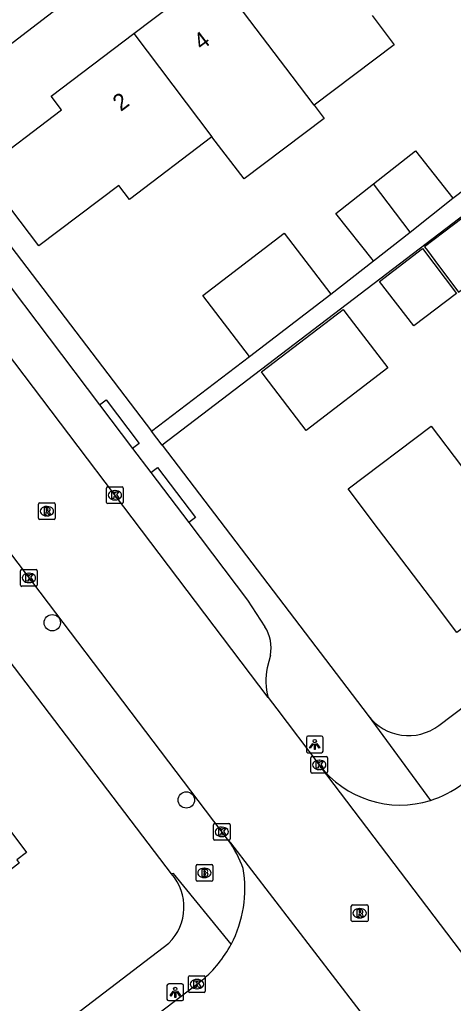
# Model space of a CAD drawing. Extents: x 160037 to 160839, y 385326 to 386441.
# Drawn here: x 160524.3 to 160550.3, y 385648.1 to 385707 of the extents above; entities that cross this region are included whole.
import ezdxf

# ---------------------------------------------------------------- set-up
doc = ezdxf.new("R2010")
doc.units = 0
for name, color, linetype in [('IMGEO_Boom', 7, 'Continuous'), ('IMGEO_Brandkraan', 7, 'Continuous'), ('IMGEO_Kolk', 7, 'Continuous'), ('IMGEO_Lichtpunt', 7, 'Continuous'), ('IMGEO_Pand', 7, 'Continuous'), ('IMGEO_Pand_nummerreeks', 7, 'Continuous'), ('IMGEO_Rijbaan_lokaal_open', 7, 'Continuous'), ('IMGEO_Rioolput', 7, 'Continuous'), ('IMGEO_Voetpad_open', 7, 'Continuous')]:
    doc.layers.add(name, color=color, linetype=linetype)

msp = doc.modelspace()

# ---------------------------------------------------------------- linework, layer by layer
at = {"layer": 'IMGEO_Boom'}
for centre in [(160526.282, 385670.878), (160534.3, 385660.27)]:
    msp.add_circle(centre, 0.489, dxfattribs=at)
at = {"layer": 'IMGEO_Brandkraan'}
for p, q in [((160534.88, 385655.48), (160534.88, 385656.332)), ((160534.955, 385656.406), (160535.807, 385656.406)), ((160535.881, 385656.332), (160535.881, 385655.48)), ((160535.368, 385656.186), (160535.393, 385656.186)), ((160535.807, 385655.406), (160534.955, 385655.406)), ((160535.391, 385655.626), (160535.366, 385655.626))]:
    msp.add_line(p, q, dxfattribs=at)
for points in [[(160534.88, 385655.48), (160534.88, 385656.332)], [(160534.955, 385656.406), (160535.807, 385656.406)], [(160535.881, 385656.332), (160535.881, 385655.48)], [(160535.228, 385656.106), (160535.228, 385655.706), (160535.441, 385655.706)], [(160535.459, 385656.106), (160535.228, 385656.106)], [(160535.407, 385656.025), (160535.353, 385656.025), (160535.353, 385655.949)], [(160535.353, 385655.949), (160535.406, 385655.949)], [(160535.415, 385655.873), (160535.353, 385655.873), (160535.353, 385655.792)], [(160535.353, 385655.792), (160535.415, 385655.792)], [(160535.807, 385655.406), (160534.955, 385655.406)]]:
    msp.add_lwpolyline(points, dxfattribs=at)
for centre, radius, start, end in [((160534.957, 385656.33), 0.0765, 91.55205, 178.44795), ((160534.957, 385656.33), 0.0765, 91.55205, 178.44795), ((160535.805, 385656.33), 0.0765, 1.55205, 88.44795), ((160535.805, 385656.33), 0.0765, 1.55205, 88.44795), ((160535.408, 385655.987), 0.0379, 267.82845, 90.93552), ((160535.416, 385655.832), 0.0404, 269.87594, 90.50774), ((160535.447, 385655.957), 0.251, 268.66757, 293.53466), ((160535.463, 385655.961), 0.145, 59.4692, 91.53667), ((160535.488, 385656.008), 0.0922, 285.51372, 58.15012), ((160535.493, 385655.816), 0.105, 301.31148, 78.98903), ((160534.957, 385655.482), 0.0765, 181.55205, 268.44795), ((160534.957, 385655.482), 0.0765, 181.55205, 268.44795), ((160535.805, 385655.482), 0.0765, 271.55205, 358.44795), ((160535.805, 385655.482), 0.0765, 271.55205, 358.44795)]:
    msp.add_arc(centre, radius, start, end, dxfattribs=at)
for centre, major_axis, ratio, start_param, end_param in [((160535.367, 385655.906), (-0.387, 0.002), 0.722429, 4.712389, 7.853982), ((160535.392, 385655.906), (-0.39, 0.002), 0.717154, 1.570796, 4.712389)]:
    msp.add_ellipse(centre, major_axis=major_axis, ratio=ratio, start_param=start_param, end_param=end_param, dxfattribs=at)
at = {"layer": 'IMGEO_Kolk'}
for p, q in [((160529.527, 385678.083), (160529.527, 385678.935)), ((160529.602, 385679.009), (160530.454, 385679.009)), ((160530.015, 385678.789), (160530.04, 385678.789)), ((160530.528, 385678.935), (160530.528, 385678.083)), ((160530.454, 385678.009), (160529.602, 385678.009)), ((160530.038, 385678.229), (160530.013, 385678.229)), ((160524.384, 385673.131), (160524.384, 385673.983)), ((160524.459, 385674.057), (160525.311, 385674.057)), ((160525.385, 385673.983), (160525.385, 385673.131)), ((160524.872, 385673.837), (160524.897, 385673.837)), ((160525.311, 385673.057), (160524.459, 385673.057)), ((160524.895, 385673.277), (160524.87, 385673.277)), ((160541.751, 385661.946), (160541.751, 385662.798)), ((160541.826, 385662.872), (160542.678, 385662.872)), ((160542.752, 385662.798), (160542.752, 385661.946)), ((160542.239, 385662.652), (160542.264, 385662.652)), ((160542.678, 385661.872), (160541.826, 385661.872)), ((160542.262, 385662.092), (160542.237, 385662.092)), ((160535.923, 385657.938), (160535.923, 385658.79)), ((160535.998, 385658.864), (160536.85, 385658.864)), ((160536.411, 385658.644), (160536.436, 385658.644)), ((160536.924, 385658.79), (160536.924, 385657.938)), ((160536.434, 385658.084), (160536.409, 385658.084)), ((160536.85, 385657.864), (160535.998, 385657.864)), ((160534.51, 385649.751), (160535.362, 385649.751)), ((160534.435, 385648.825), (160534.435, 385649.677)), ((160534.923, 385649.531), (160534.948, 385649.531)), ((160535.436, 385649.677), (160535.436, 385648.825)), ((160535.362, 385648.751), (160534.51, 385648.751)), ((160534.946, 385648.971), (160534.921, 385648.971))]:
    msp.add_line(p, q, dxfattribs=at)
for points in [[(160529.527, 385678.083), (160529.527, 385678.935)], [(160529.602, 385679.009), (160530.454, 385679.009)], [(160529.848, 385678.709), (160529.971, 385678.709), (160529.971, 385678.558), (160530.101, 385678.709), (160530.265, 385678.709), (160530.119, 385678.558), (160530.272, 385678.309), (160530.12, 385678.309), (160530.035, 385678.473), (160529.971, 385678.406), (160529.971, 385678.309), (160529.848, 385678.309), (160529.848, 385678.709)], [(160530.528, 385678.935), (160530.528, 385678.083)], [(160530.454, 385678.009), (160529.602, 385678.009)], [(160524.384, 385673.131), (160524.384, 385673.983)], [(160524.459, 385674.057), (160525.311, 385674.057)], [(160525.385, 385673.983), (160525.385, 385673.131)], [(160524.705, 385673.757), (160524.828, 385673.757), (160524.828, 385673.606), (160524.958, 385673.757), (160525.122, 385673.757), (160524.976, 385673.606), (160525.129, 385673.357), (160524.977, 385673.357), (160524.892, 385673.521), (160524.828, 385673.454), (160524.828, 385673.357), (160524.705, 385673.357), (160524.705, 385673.757)], [(160525.311, 385673.057), (160524.459, 385673.057)], [(160541.751, 385661.946), (160541.751, 385662.798)], [(160541.826, 385662.872), (160542.678, 385662.872)], [(160542.752, 385662.798), (160542.752, 385661.946)], [(160542.072, 385662.572), (160542.195, 385662.572), (160542.195, 385662.421), (160542.325, 385662.572), (160542.489, 385662.572), (160542.343, 385662.421), (160542.496, 385662.172), (160542.344, 385662.172), (160542.259, 385662.336), (160542.195, 385662.269), (160542.195, 385662.172), (160542.072, 385662.172), (160542.072, 385662.572)], [(160542.678, 385661.872), (160541.826, 385661.872)], [(160535.923, 385657.938), (160535.923, 385658.79)], [(160535.998, 385658.864), (160536.85, 385658.864)], [(160536.924, 385658.79), (160536.924, 385657.938)], [(160536.244, 385658.564), (160536.367, 385658.564), (160536.367, 385658.413), (160536.497, 385658.564), (160536.661, 385658.564), (160536.515, 385658.413), (160536.668, 385658.164), (160536.516, 385658.164), (160536.431, 385658.328), (160536.367, 385658.261), (160536.367, 385658.164), (160536.244, 385658.164), (160536.244, 385658.564)], [(160536.85, 385657.864), (160535.998, 385657.864)], [(160534.51, 385649.751), (160535.362, 385649.751)], [(160534.435, 385648.825), (160534.435, 385649.677)], [(160534.756, 385649.451), (160534.879, 385649.451), (160534.879, 385649.3), (160535.009, 385649.451), (160535.173, 385649.451), (160535.027, 385649.3), (160535.18, 385649.051), (160535.028, 385649.051), (160534.943, 385649.215), (160534.879, 385649.148), (160534.879, 385649.051), (160534.756, 385649.051), (160534.756, 385649.451)], [(160535.436, 385649.677), (160535.436, 385648.825)], [(160535.362, 385648.751), (160534.51, 385648.751)]]:
    msp.add_lwpolyline(points, dxfattribs=at)
for centre, start, end in [((160529.604, 385678.933), 91.55205, 178.44795), ((160529.604, 385678.933), 91.55205, 178.44795), ((160530.452, 385678.933), 1.55205, 88.44795), ((160530.452, 385678.933), 1.55205, 88.44795), ((160529.604, 385678.085), 181.55205, 268.44795), ((160529.604, 385678.085), 181.55205, 268.44795), ((160530.452, 385678.085), 271.55205, 358.44795), ((160530.452, 385678.085), 271.55205, 358.44795), ((160524.461, 385673.981), 91.55205, 178.44795), ((160524.461, 385673.981), 91.55205, 178.44795), ((160525.309, 385673.981), 1.55205, 88.44795), ((160525.309, 385673.981), 1.55205, 88.44795), ((160524.461, 385673.133), 181.55205, 268.44795), ((160524.461, 385673.133), 181.55205, 268.44795), ((160525.309, 385673.133), 271.55205, 358.44795), ((160525.309, 385673.133), 271.55205, 358.44795), ((160541.828, 385662.796), 91.55205, 178.44795), ((160541.828, 385662.796), 91.55205, 178.44795), ((160542.676, 385662.796), 1.55205, 88.44795), ((160542.676, 385662.796), 1.55205, 88.44795), ((160541.828, 385661.948), 181.55205, 268.44795), ((160541.828, 385661.948), 181.55205, 268.44795), ((160542.676, 385661.948), 271.55205, 358.44795), ((160542.676, 385661.948), 271.55205, 358.44795), ((160536, 385658.788), 91.55205, 178.44795), ((160536, 385658.788), 91.55205, 178.44795), ((160536.848, 385658.788), 1.55205, 88.44795), ((160536.848, 385658.788), 1.55205, 88.44795), ((160536, 385657.94), 181.55205, 268.44795), ((160536, 385657.94), 181.55205, 268.44795), ((160536.848, 385657.94), 271.55205, 358.44795), ((160536.848, 385657.94), 271.55205, 358.44795), ((160534.512, 385649.675), 91.55205, 178.44795), ((160534.512, 385649.675), 91.55205, 178.44795), ((160535.36, 385649.675), 1.55205, 88.44795), ((160535.36, 385649.675), 1.55205, 88.44795), ((160534.512, 385648.827), 181.55205, 268.44795), ((160534.512, 385648.827), 181.55205, 268.44795), ((160535.36, 385648.827), 271.55205, 358.44795), ((160535.36, 385648.827), 271.55205, 358.44795)]:
    msp.add_arc(centre, 0.0765, start, end, dxfattribs=at)
for centre, major_axis, ratio, start_param, end_param in [((160530.014, 385678.509), (-0.387, 0.002), 0.722429, 4.712389, 7.853982), ((160530.039, 385678.509), (-0.39, 0.002), 0.717154, 1.570796, 4.712389), ((160524.871, 385673.557), (-0.387, 0.002), 0.722429, 4.712389, 7.853982), ((160524.896, 385673.557), (-0.39, 0.002), 0.717154, 1.570796, 4.712389), ((160542.238, 385662.372), (-0.387, 0.002), 0.722429, 4.712389, 7.853982), ((160542.263, 385662.372), (-0.39, 0.002), 0.717154, 1.570796, 4.712389), ((160536.41, 385658.364), (-0.387, 0.002), 0.722429, 4.712389, 7.853982), ((160536.435, 385658.364), (-0.39, 0.002), 0.717154, 1.570796, 4.712389), ((160534.922, 385649.251), (-0.387, 0.002), 0.722429, 4.712389, 7.853982), ((160534.947, 385649.251), (-0.39, 0.002), 0.717154, 1.570796, 4.712389)]:
    msp.add_ellipse(centre, major_axis=major_axis, ratio=ratio, start_param=start_param, end_param=end_param, dxfattribs=at)
at = {"layer": 'IMGEO_Lichtpunt'}
for p, q in [((160541.484, 385663.996), (160541.484, 385663.189)), ((160541.484, 385663.996), (160541.484, 385663.189)), ((160542.386, 385664.091), (160541.578, 385664.091)), ((160542.386, 385664.091), (160541.578, 385664.091)), ((160542.48, 385663.189), (160542.48, 385663.996)), ((160542.48, 385663.189), (160542.48, 385663.996)), ((160541.578, 385663.095), (160542.386, 385663.095)), ((160541.578, 385663.095), (160542.386, 385663.095)), ((160533.141, 385649.163), (160533.141, 385648.356)), ((160533.141, 385649.163), (160533.141, 385648.356)), ((160534.043, 385649.258), (160533.235, 385649.258)), ((160534.043, 385649.258), (160533.235, 385649.258)), ((160534.137, 385648.356), (160534.137, 385649.163)), ((160534.137, 385648.356), (160534.137, 385649.163)), ((160533.235, 385648.262), (160534.043, 385648.262)), ((160533.235, 385648.262), (160534.043, 385648.262))]:
    msp.add_line(p, q, dxfattribs=at)
for points in [[(160541.858, 385663.66), (160541.897, 385663.632), (160541.709, 385663.37), (160541.671, 385663.397), (160541.858, 385663.66)], [(160541.96, 385663.612), (160542.007, 385663.612), (160542.007, 385663.29), (160541.96, 385663.29), (160541.96, 385663.612)], [(160542.07, 385663.632), (160542.108, 385663.659), (160542.295, 385663.397), (160542.256, 385663.369), (160542.07, 385663.632)], [(160533.515, 385648.827), (160533.554, 385648.799), (160533.366, 385648.537), (160533.328, 385648.564), (160533.515, 385648.827)], [(160533.617, 385648.779), (160533.664, 385648.779), (160533.664, 385648.457), (160533.617, 385648.457), (160533.617, 385648.779)], [(160533.727, 385648.799), (160533.765, 385648.826), (160533.952, 385648.564), (160533.913, 385648.536), (160533.727, 385648.799)]]:
    msp.add_lwpolyline(points, dxfattribs=at)
for centre in [(160541.983, 385663.794), (160533.64, 385648.961)]:
    msp.add_circle(centre, 0.0994, dxfattribs=at)
for centre, start, end in [((160541.578, 385663.996), 90, 180), ((160541.578, 385663.996), 90, 180), ((160542.386, 385663.996), 0, 90), ((160542.386, 385663.996), 0, 90), ((160541.578, 385663.189), 180, 270), ((160541.578, 385663.189), 180, 270), ((160542.386, 385663.189), 270, 0), ((160542.386, 385663.189), 270, 360), ((160533.235, 385649.163), 90, 180), ((160533.235, 385649.163), 90, 180), ((160534.043, 385649.163), 0, 90), ((160534.043, 385649.163), 0, 90), ((160533.235, 385648.356), 180, 270), ((160533.235, 385648.356), 180, 270), ((160534.043, 385648.356), 270, 0), ((160534.043, 385648.356), 270, 360)]:
    msp.add_arc(centre, 0.0946, start, end, dxfattribs=at)
at = {"layer": 'IMGEO_Pand'}
for points in [[(160531.164, 385706.148), (160535.946, 385709.773)], [(160541.946, 385701.851), (160540.63, 385703.592), (160535.946, 385709.773)], [(160545.412, 385707.216), (160546.735, 385705.47), (160541.946, 385701.851)], [(160535.833, 385699.956), (160530.89, 385696.209), (160530.252, 385697.051), (160525.473, 385693.428), (160522.048, 385697.946), (160526.828, 385701.569), (160526.206, 385702.39), (160531.164, 385706.148)], [(160531.164, 385706.148), (160535.833, 385699.956)], [(160541.946, 385701.851), (160542.545, 385701.058), (160537.767, 385697.437), (160535.833, 385699.956)], [(160545.501, 385697.148), (160548.011, 385699.124), (160550.249, 385696.281)], [(160545.49, 385692.533), (160543.251, 385695.376), (160545.501, 385697.148)], [(160547.684, 385694.261), (160545.501, 385697.148)], [(160547.684, 385694.261), (160550.249, 385696.281)], [(160548.554, 385693.366), (160548.719, 385693.147), (160549.16, 385692.559), (160550.588, 385690.658), (160552.911, 385692.402), (160551.042, 385694.891), (160550.86, 385695.133), (160548.554, 385693.366)], [(160538.081, 385686.808), (160535.29, 385690.452), (160540.161, 385694.184), (160542.953, 385690.541)], [(160545.49, 385692.533), (160547.684, 385694.261)], [(160545.848, 385691.293), (160548.431, 385693.272), (160550.472, 385690.572), (160547.902, 385688.642), (160545.848, 385691.293)], [(160538.081, 385686.808), (160542.953, 385690.541)], [(160538.792, 385685.887), (160543.679, 385689.631), (160543.847, 385689.412), (160544.506, 385688.552), (160546.36, 385686.131), (160541.473, 385682.387), (160538.96, 385685.668), (160538.792, 385685.887)], [(160555.444, 385674.058), (160550.487, 385670.301), (160548.912, 385672.38), (160545.803, 385676.482), (160543.981, 385678.886), (160548.939, 385682.642), (160550.76, 385680.239)], [(160520.413, 385661.289), (160521.655, 385659.651), (160522.406, 385660.22), (160524.745, 385657.135), (160524.157, 385656.689), (160524.303, 385656.497), (160517.653, 385651.456), (160513.927, 385656.371)]]:
    msp.add_lwpolyline(points, dxfattribs=at)
at = {"layer": 'IMGEO_Rijbaan_lokaal_open'}
for points in [[(160539.192, 385666.41), (160518.609, 385693.58)], [(160536.815, 385657.852), (160519.703, 385680.381), (160511.005, 385691.824)], [(160539.192, 385666.41), (160539.718, 385665.716), (160542.249, 385662.375)], [(160542.249, 385662.375), (160542.312, 385662.277), (160551.877, 385649.668)], [(160547.128, 385644.454), (160547.022, 385644.629), (160536.957, 385657.707), (160536.815, 385657.852)], [(160515.733, 385634.63), (160520, 385637.876), (160535.257, 385649.493)]]:
    msp.add_lwpolyline(points, dxfattribs=at)
for centre, radius, start, end in [((160547.096, 385666.05), 6.082, 217.16657, 287.38278), ((160547.102, 385666.035), 6.067, 287.36489, 307.48226), ((160532.25, 385654.389), 5.729, 18.13757, 37.18243), ((160530.668, 385654.951), 7.133, 332.26582, 9.8628), ((160530.663, 385654.96), 7.14, 310.0403, 332.22317)]:
    msp.add_arc(centre, radius, start, end, dxfattribs=at)
at = {"layer": 'IMGEO_Rioolput'}
for p, q in [((160525.531, 385678.054), (160526.383, 385678.054)), ((160525.456, 385677.128), (160525.456, 385677.98)), ((160525.944, 385677.834), (160525.969, 385677.834)), ((160526.457, 385677.98), (160526.457, 385677.128)), ((160526.383, 385677.054), (160525.531, 385677.054)), ((160525.967, 385677.274), (160525.942, 385677.274)), ((160544.17, 385653.065), (160544.17, 385653.917)), ((160544.245, 385653.991), (160545.097, 385653.991)), ((160545.171, 385653.917), (160545.171, 385653.065)), ((160544.658, 385653.771), (160544.683, 385653.771)), ((160545.097, 385652.991), (160544.245, 385652.991)), ((160544.681, 385653.211), (160544.656, 385653.211))]:
    msp.add_line(p, q, dxfattribs=at)
for points in [[(160525.531, 385678.054), (160526.383, 385678.054)], [(160525.456, 385677.128), (160525.456, 385677.98)], [(160526.045, 385677.752), (160525.793, 385677.754), (160525.793, 385677.354)], [(160525.793, 385677.354), (160525.917, 385677.354), (160525.917, 385677.516), (160525.928, 385677.516)], [(160525.971, 385677.673), (160525.917, 385677.673), (160525.917, 385677.592)], [(160525.917, 385677.592), (160525.969, 385677.592)], [(160525.975, 385677.487), (160526.046, 385677.354), (160526.186, 385677.354), (160526.121, 385677.48)], [(160526.457, 385677.98), (160526.457, 385677.128)], [(160526.383, 385677.054), (160525.531, 385677.054)], [(160544.17, 385653.065), (160544.17, 385653.917)], [(160544.245, 385653.991), (160545.097, 385653.991)], [(160545.171, 385653.917), (160545.171, 385653.065)], [(160544.759, 385653.689), (160544.507, 385653.691), (160544.507, 385653.291)], [(160544.507, 385653.291), (160544.631, 385653.291), (160544.631, 385653.453), (160544.642, 385653.453)], [(160544.685, 385653.61), (160544.631, 385653.61), (160544.631, 385653.529)], [(160544.631, 385653.529), (160544.683, 385653.529)], [(160544.689, 385653.424), (160544.76, 385653.291), (160544.9, 385653.291), (160544.835, 385653.417)], [(160545.097, 385652.991), (160544.245, 385652.991)]]:
    msp.add_lwpolyline(points, dxfattribs=at)
for centre, radius, start, end in [((160525.533, 385677.978), 0.0765, 91.55205, 178.44795), ((160525.533, 385677.978), 0.0765, 91.55205, 178.44795), ((160526.381, 385677.978), 0.0765, 1.55205, 88.44795), ((160526.381, 385677.978), 0.0765, 1.55205, 88.44795), ((160525.927, 385677.463), 0.0533, 26.02933, 88.69889), ((160525.953, 385677.781), 0.19, 274.7715, 282.96867), ((160525.977, 385677.577), 0.0964, 77.00612, 93.18647), ((160525.991, 385677.634), 0.0378, 276.66336, 79.67722), ((160526.044, 385677.642), 0.109, 350.36119, 89.41601), ((160526.042, 385677.642), 0.112, 277.58423, 350.98172), ((160526.026, 385677.427), 0.108, 29.51342, 73.79051), ((160525.533, 385677.13), 0.0765, 181.55205, 268.44795), ((160525.533, 385677.13), 0.0765, 181.55205, 268.44795), ((160526.381, 385677.13), 0.0765, 271.55205, 358.44795), ((160526.381, 385677.13), 0.0765, 271.55205, 358.44795), ((160544.247, 385653.915), 0.0765, 91.55205, 178.44795), ((160544.247, 385653.915), 0.0765, 91.55205, 178.44795), ((160545.095, 385653.915), 0.0765, 1.55205, 88.44795), ((160545.095, 385653.915), 0.0765, 1.55205, 88.44795), ((160544.641, 385653.4), 0.0533, 26.02933, 88.69889), ((160544.667, 385653.718), 0.19, 274.7715, 282.96867), ((160544.691, 385653.514), 0.0964, 77.00612, 93.18647), ((160544.705, 385653.571), 0.0378, 276.66336, 79.67722), ((160544.758, 385653.579), 0.109, 350.36119, 89.41601), ((160544.756, 385653.579), 0.112, 277.58423, 350.98172), ((160544.74, 385653.364), 0.108, 29.51342, 73.79051), ((160544.247, 385653.067), 0.0765, 181.55205, 268.44795), ((160544.247, 385653.067), 0.0765, 181.55205, 268.44795), ((160545.095, 385653.067), 0.0765, 271.55205, 358.44795), ((160545.095, 385653.067), 0.0765, 271.55205, 358.44795)]:
    msp.add_arc(centre, radius, start, end, dxfattribs=at)
for centre, major_axis, ratio, start_param, end_param in [((160525.943, 385677.554), (-0.387, 0.002), 0.722429, 4.712389, 7.853982), ((160525.968, 385677.554), (-0.39, 0.002), 0.717154, 1.570796, 4.712389), ((160544.657, 385653.491), (-0.387, 0.002), 0.722429, 4.712389, 7.853982), ((160544.682, 385653.491), (-0.39, 0.002), 0.717154, 1.570796, 4.712389)]:
    msp.add_ellipse(centre, major_axis=major_axis, ratio=ratio, start_param=start_param, end_param=end_param, dxfattribs=at)
at = {"layer": 'IMGEO_Voetpad_open'}
for points in [[(160533.41, 385655.858), (160500, 385699.746), (160471.388, 385737.358)], [(160557.562, 385731.421), (160520.069, 385702.649)], [(160550.249, 385696.281), (160554.645, 385699.623)], [(160519.574, 385698.928), (160532.215, 385682.338)], [(160555.368, 385698.673), (160532.846, 385681.511)], [(160549.415, 385664.734), (160586.71, 385692.941)], [(160542.953, 385690.541), (160545.49, 385692.533)], [(160523.066, 385691.889), (160529.106, 385683.916)], [(160532.215, 385682.338), (160538.081, 385686.808)], [(160529.106, 385683.916), (160529.504, 385684.218), (160531.479, 385681.611), (160531.08, 385681.309)], [(160529.106, 385683.916), (160531.08, 385681.309)], [(160532.846, 385681.511), (160532.215, 385682.338)], [(160531.08, 385681.309), (160532.173, 385679.866)], [(160532.846, 385681.511), (160545.185, 385665.318)], [(160532.173, 385679.866), (160532.572, 385680.168), (160534.842, 385677.171), (160534.443, 385676.869)], [(160532.173, 385679.866), (160534.443, 385676.869)], [(160534.443, 385676.869), (160537.965, 385672.22), (160538.991, 385670.641)], [(160539.326, 385668.929), (160539.13, 385668.18)], [(160545.185, 385665.318), (160548.913, 385660.245)], [(160536.981, 385651.632), (160533.531, 385655.877), (160533.41, 385655.858)], [(160514.628, 385637.478), (160533.261, 385651.698)]]:
    msp.add_lwpolyline(points, dxfattribs=at)
for centre, radius, start, end in [((160537.089, 385669.38), 2.282, 348.60374, 33.53947), ((160543.002, 385667.43), 3.944, 169.03043, 194.98187), ((160547.592, 385667.145), 3.022, 217.18723, 307.09148), ((160531.119, 385653.857), 3.041, 314.76704, 41.13035)]:
    msp.add_arc(centre, radius, start, end, dxfattribs=at)

# ---------------------------------------------------------------- texts
at = {"layer": 'IMGEO_Pand_nummerreeks'}
for s, rotation, p in [('4', 37.16204, (160535.216, 385705.103)), ('2', 37.16012, (160530.382, 385701.44))]:
    msp.add_text(s, height=1, rotation=rotation, dxfattribs=at).set_placement(p)

doc.saveas('drawing.dxf')
